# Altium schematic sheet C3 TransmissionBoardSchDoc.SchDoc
size A3; SheetNumber: 1; SheetTotal: 1; ENG_APP_DATE: --/--/--; DSN_APP_DATE: --/--/--; CHK_APP_DATE: --/--/--
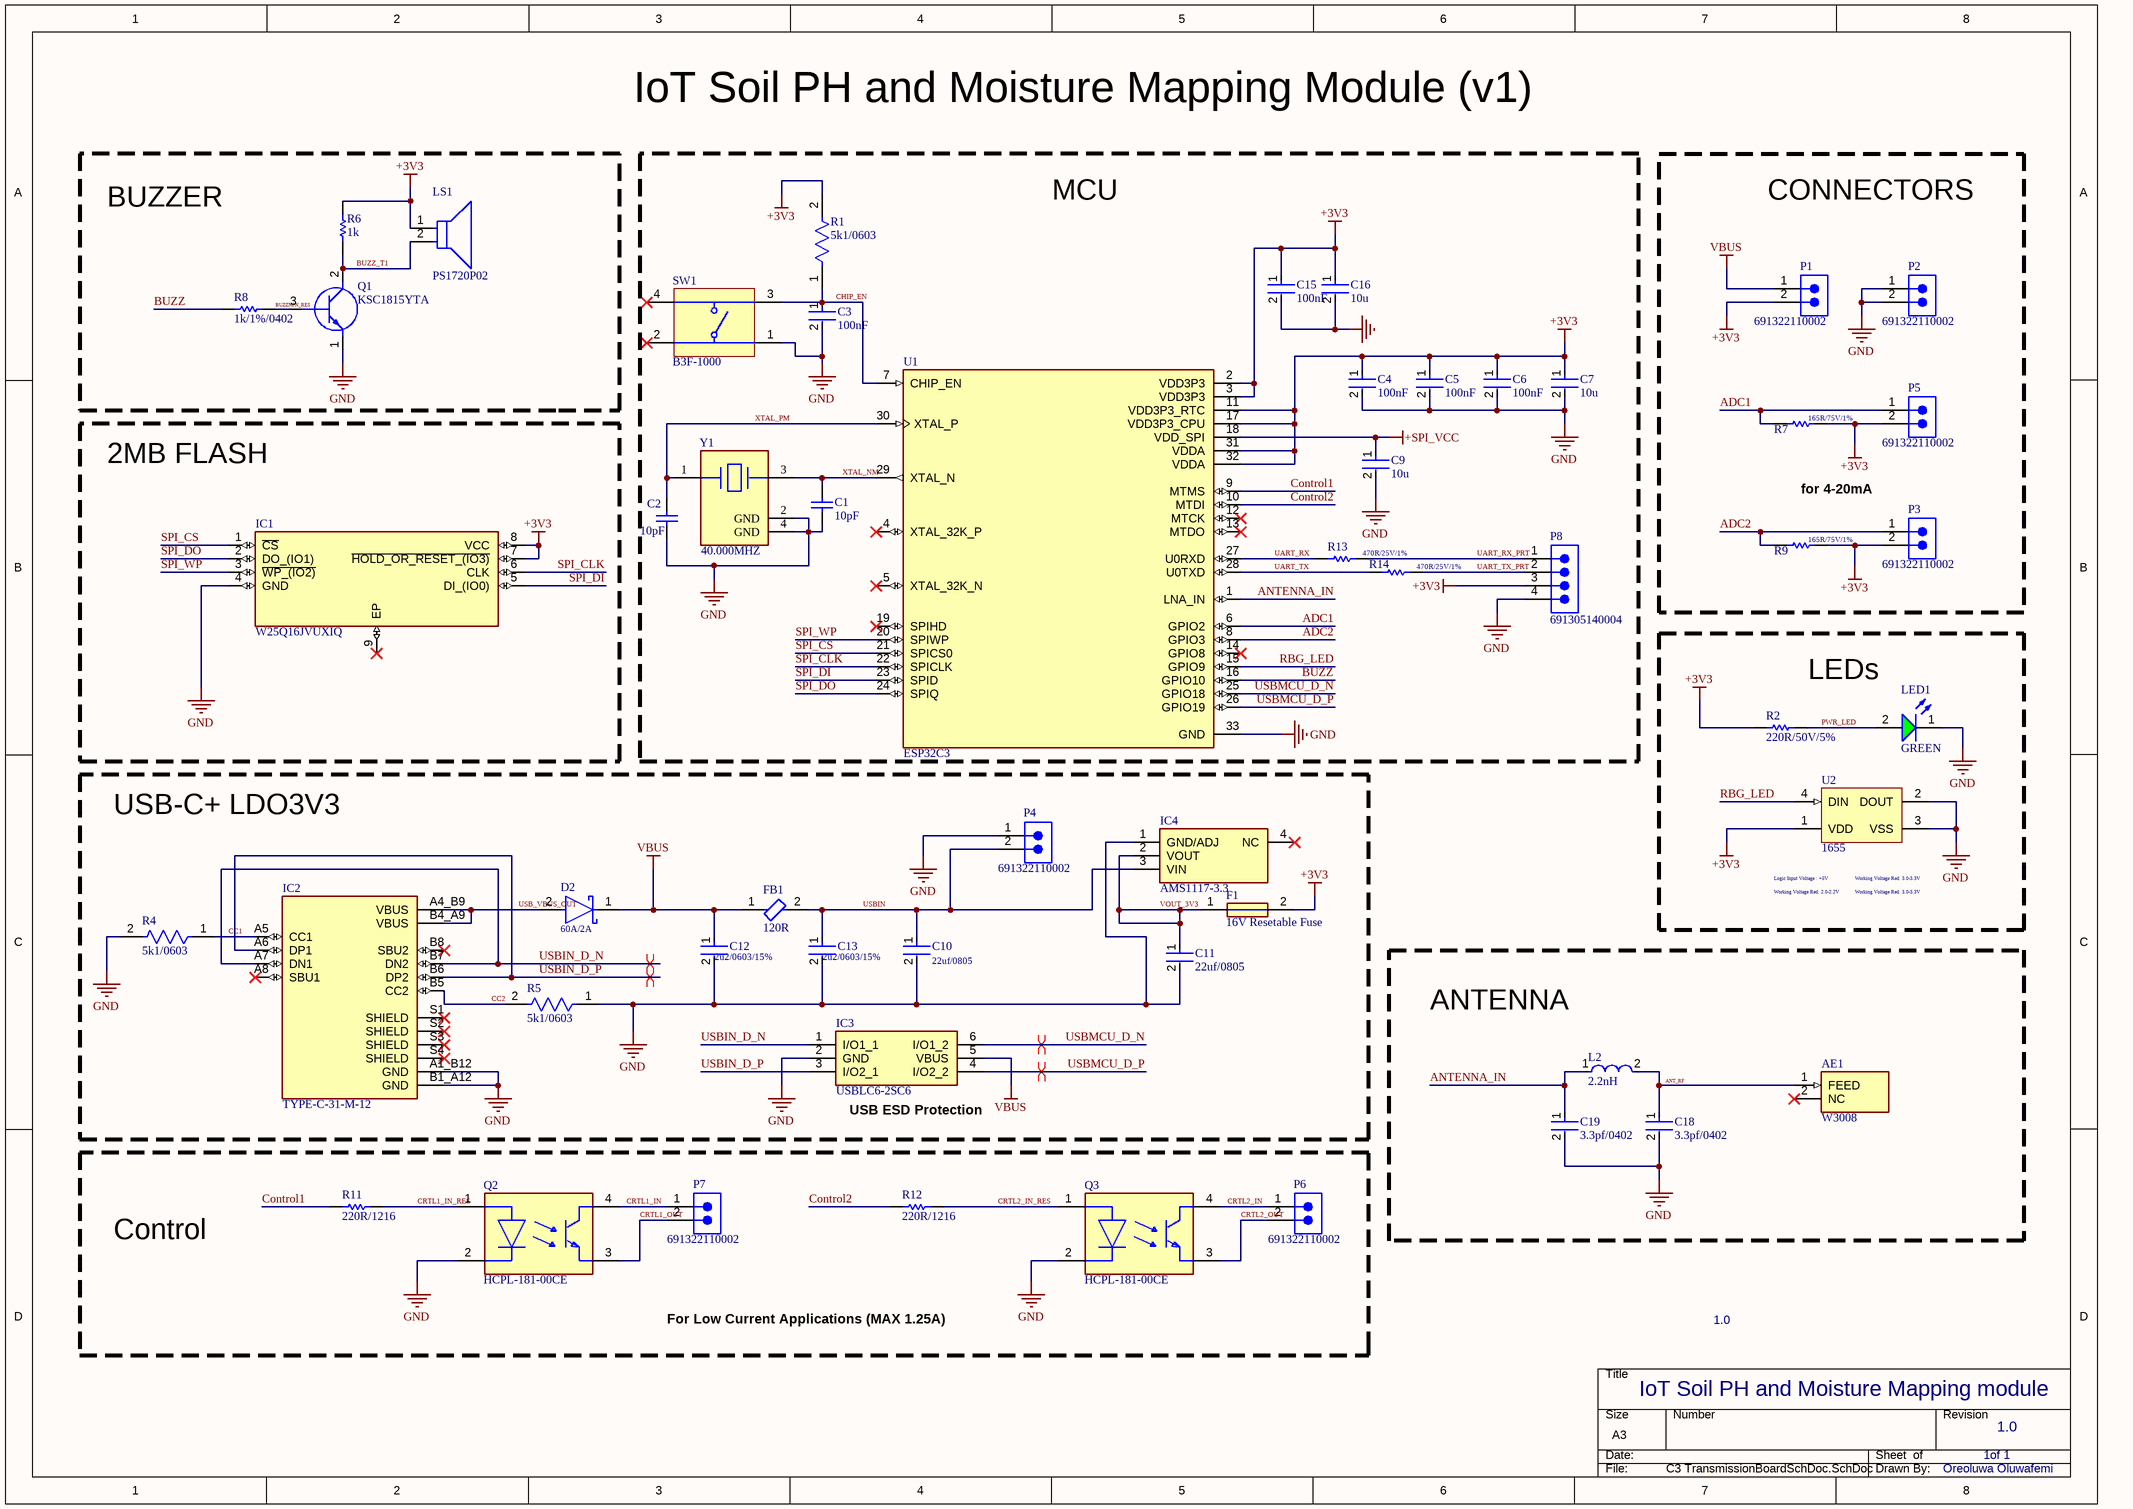
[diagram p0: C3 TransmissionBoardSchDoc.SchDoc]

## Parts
AE1  W3008  [ANTC3216X115N]
C1  10pF  [CAPC1608X90X35LL10T15]
C2  10pF  [CAPC1608X90X35LL10T15]
C3  100nF  [FP-GRM033-0_03-MFG]
C4  100nF  [FP-GRM033-0_03-MFG]
C5  100nF  [FP-GRM033-0_03-MFG]
C6  100nF  [FP-GRM033-0_03-MFG]
C7  10u  [FP-GRM188-0_1-e0_2_0_55-IPC_A]
C9  10u  [FP-GRM188-0_1-e0_2_0_55-IPC_A]
C10  22uf/0805  [FP-C0805C226M9PACTU-MFG]
C11  22uf/0805  [FP-C0805C226M9PACTU-MFG]
C12  2u2/0603/15%  [FP-GRM188-0_1-e0_2_0_5-MFG]
C13  2u2/0603/15%  [FP-GRM188-0_1-e0_2_0_5-MFG]
C15  100nF  [FP-GRM033-0_03-MFG]
C16  10u  [FP-GRM188-0_1-e0_2_0_55-IPC_A]
C18  3.3pf/0402  [FP-GJM155-0_05-IPC_B]
C19  3.3pf/0402  [FP-GJM155-0_05-IPC_B]
D2  60A/2A  [FP-SOD123W-MFG]
F1  16V Resetable Fuse  [FUSC4632X160N]
FB1  120R  [FP-BLM18-0_15-t0_8-IPC_A]
IC1  W25Q16JVUXIQ  [SON50P300X200X60-9N]
IC2  TYPE-C-31-M-12  [HRO_TYPE-C-31-M-12]
IC3  USBLC6-2SC6  [SOT95P280X145-6N]
IC4  AMS1117-3.3  [SOT229P700X180-4N]
L2  2.2nH  [FP-LQW18AN_80-MFG]
LED1  GREEN  [WL-SMCW_0603_150060xx75000]
LS1  PS1720P02  [FP-PS1720P02-MFG]
P1  691322110002  [691322110002]
P2  691322110002  [691322110002]
P3  691322110002  [691322110002]
P4  691322110002  [691322110002]
P5  691322110002  [691322110002]
P6  691322110002  [691322110002]
P7  691322110002  [691322110002]
P8  691305140004  [691305140004]
Q1  KSC1815YTA  [BC33740TA]
Q2  HCPL-181-00CE  [FP-SO-4-MFG]
Q3  HCPL-181-00CE  [FP-SO-4-MFG]
R1  5k1/0603  [FP-RT0603-MFG]
R2  220R/50V/5%  [RESC1005X40X25NL05T10]
R4  5k1/0603  [FP-RT0603-MFG]
R5  5k1/0603  [FP-RT0603-MFG]
R6  1k  [RESC1005X40X25NL05T05]
R7  165R/75V/1%  [RESC1608X55X30NL15T15]
R8  1k/1%/0402  [RESC1005X40X25NL05T05]
R9  165R/75V/1%  [RESC1608X55X30NL15T15]
R11  220R/1216  [RESC3216X60X45ML10T20]
R12  220R/1216  [RESC3216X60X45ML10T20]
R13  470R/25V/1%  [RESC0603X26X15LL03T05]
R14  470R/25V/1%  [RESC0603X26X15LL03T05]
SW1  B3F-1000  [OMRON-B3F-1000-4_V]
U1  ESP32C3  [QFN32_5X5MM]
U2  1655  [ADA-RGB-1655_V]
Y1  40.000MHZ  [FP-ABM8-MFG]

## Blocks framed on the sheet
MCU: C1-C7 C9 C15 C16 P8 R1 R13 R14 SW1 U1 Y1
CONNECTORS: P1-P3 P5 R7 R9
2MB FLASH: IC1
USB-C+ LDO3V3: C10-C13 D2 F1 FB1 IC2-IC4 P4 R4 R5
Control: P6 P7 Q2 Q3 R11 R12

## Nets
+3V3: C4.1 C5.1 C6.1 C7.1 C15.1 C16.1 F1.2 IC1.7(~{HOLD_OR_RESET_(IO3)}) IC1.8(VCC) LS1.1 P1.2 P3.2 P5.2 P8.3 R1.2 R2.1 R6.2 R7.2 R9.2 U1.2(VDD3P3) U1.3(VDD3P3) U1.11(VDD3P3_RTC) U1.17(VDD3P3_CPU) U1.31(VDDA) U1.32(VDDA) U2.1(VDD)
+SPI_VCC: C9.1 U1.18(VDD_SPI)
GND: C1.1 C2.1 C3.2 C4.2 C5.2 C6.2 C7.2 C9.2 C10.2 C11.2 C12.2 C13.2 C15.2 C16.2 C18.2 C19.2 IC1.4(GND) IC2.A1_B12(GND) IC2.B1_A12(GND) IC3.2(GND) IC4.1(GND/ADJ) LED1.1(K) P2.1 P2.2 P4.1 P8.4 Q1.1(E) Q2.2(C) Q3.2(C) R4.2 R5.1 SW1.1 U1.33(GND) U2.2(DOUT) U2.3(VSS) Y1.2(GND) Y1.4(GND)
VBUS: C12.1 D2.1(C) FB1.1 IC3.5(VBUS) P1.1
ADC1: P5.1 R7.1 U1.6(GPIO2)
ADC2: P3.1 R9.1 U1.8(GPIO3)
ANT_RF: AE1.1(FEED) C18.1 L2.2
ANTENNA_IN: C19.1 L2.1 U1.1(LNA_IN)
BUZZ: R8.2 U1.16(GPIO10)
BUZZ_T1: LS1.2 Q1.2(C) R6.1
BUZZNPN_RES: Q1.3(B) R8.1
CC1: IC2.A5(CC1) R4.1
CC2: IC2.B5(CC2) R5.2
CHIP_EN: C3.1 R1.1 SW1.3 U1.7(CHIP_EN)
Control1: R11.1 U1.9(MTMS)
Control2: R12.1 U1.10(MTDI)
CRTL1_IN: P7.1 Q2.4(C)
CRTL1_IN_RES: Q2.1(A) R11.2
CRTL1_OUT: P7.2 Q2.3(E)
CRTL2_IN: P6.1 Q3.4(C)
CRTL2_IN_RES: Q3.1(A) R12.2
CRTL2_OUT: P6.2 Q3.3(E)
PWR_LED: LED1.2(A) R2.2
RBG_LED: U1.15(GPIO9) U2.4(DIN)
SPI_CLK: IC1.6(CLK) U1.22(SPICLK)
SPI_CS: IC1.1(~{CS}) U1.21(SPICS0)
SPI_DI: IC1.5(DI_(IO0)) U1.23(SPID)
SPI_DO: IC1.2(DO_(IO1)) U1.24(SPIQ)
SPI_WP: IC1.3(~{WP_(IO2)}) U1.20(SPIWP)
UART_RX: R13.1 U1.27(U0RXD)
UART_RX_PRT: P8.1 R13.2
UART_TX: R14.1 U1.28(U0TXD)
UART_TX_PRT: P8.2 R14.2
USB_VBUS_OUT: D2.2(A) IC2.A4_B9(VBUS) IC2.B4_A9(VBUS)
USBIN: C10.1 C13.1 FB1.2 IC4.3(VIN) P4.2
USBIN_D_N: IC2.A7(DN1) IC2.B7(DN2) IC3.1(I/O1_1)
USBIN_D_P: IC2.A6(DP1) IC2.B6(DP2) IC3.3(I/O2_1)
USBMCU_D_N: IC3.6(I/O1_2) U1.25(GPIO18)
USBMCU_D_P: IC3.4(I/O2_2) U1.26(GPIO19)
VOUT_3V3: C11.1 F1.1 IC4.2(VOUT)
XTAL_NM: C1.2 U1.29(XTAL_N) Y1.3
XTAL_PM: C2.2 U1.30(XTAL_P) Y1.1

Not connected (* = marked no-connect by the designer): AE1 2(NC)*; IC1 9(EP)*; IC2 A8(SBU1)* B8(SBU2)* S1(SHIELD)* S2(SHIELD)* S3(SHIELD)* S4(SHIELD)*; IC4 4(NC)*; SW1 2* 4*; U1 4(XTAL_32K_P)* 5(XTAL_32K_N)* 12(MTCK)* 13(MTDO)* 14(GPIO8)* 19(SPIHD)*

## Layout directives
differential pair; differential pair class DIF_USB: USBIN_D_N, USBIN_D_P, USBMCU_D_N, USBMCU_D_P

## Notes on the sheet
- IoT Soil PH and Moisture Mapping Module (v1)
- BUZZER
- for 4-20mA
- LEDs
- (near U2) Logic Input Voltage : +5V
- Working Voltage Red: 2.0-2.2V
- (near U2) Working Voltage Red: 3.0-3.3V
- Working Voltage Red: 3.0-3.3V
- ANTENNA
- (near IC3) USB ESD Protection
- For Low Current Applications (MAX 1.25A)
- 1.0
- IoT Soil PH and Moisture Mapping module
- 1of 1
- Oreoluwa Oluwafemi

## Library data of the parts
AE1 = W3008: Antenna; Manufacturer_Name: PULS
C1 C2 = CMP-2006-02592-1: Part Number: GRM1885C1H100JA01D; Manufacturer: Murata
C3-C6 C15 = CMP-06035-000062-2: Chip Multilayer Ceramic Capacitors for General Purpose, 0201, 0.10uF, X5R, 15%, 10%, 6.3V
C7 C9 C16 = CMP-2006-02792-2: Chip Multilayer Ceramic Capacitors for General Purpose, 0603, 10uF, X5R, 15%, 20%, 6.3V
C10 C11 = CMP-2007-01021-2: CAP CER 22UF 6.3V X5R 0805; Tolerance: 20%; Dielectric Material: Ceramic; Dissipation Factor: 5%
C12 C13 = CMP-2006-02836-2: Chip Multilayer Ceramic Capacitors for General Purpose, 0603, 2.2uF, X7R, 15%, 10%, 10V
C18 C19 = CMP-2008-03847-2: Multi-Layer Ceramic Capacitor 3.3pF C0G  ±0.25pF 0402 Paper T/R; Voltage: 50V
D2 = CMP-14398-000040-1: DIODE SCHOTTKY 60V 2A CFP3
F1 = MF-MSMF250_16X: Fuse; Manufacturer_Name: Bourns; Manufacturer_Part_Number: MF-MSMF250/16X
FB1 = CMP-0686-00557-7: Chip Ferrite Bead, 0603, 120Ω @ 100MHz, 0.05Ω, 25%, 2A; Number of Circuits: 1; Shielding: Unshielded; Material: Steel; DC Resistance (DCR): 50mR
IC1 = CMP-031-00015-1: NOR Flash Serial (SPI, Dual SPI, Quad SPI) 3V/3.3V 16M-bit 2M x 8 6ns 8-Pin USON EP T/R; MF: Winbond
IC2 = CMP-002-00071-1: USB Connectors 24 Receptacle 1 8.94*7.3mm RoHS; MF: HRO Electronics Co., Ltd.
IC3 = USBLC6-2SC6: Integrated Circuit; Manufacturer_Name: STMicroelectronics
IC4 = AMS1117-3.3: Integrated Circuit; Manufacturer_Name: Advanced
L2 = CMP-06042-009804-1: Wire Wound RF Inductor 2.2nH ±0.2nH 3200mA 0.018Ω 0603 (1608); Test Frequency: 100MHz; DC Resistance (DCR): 18mR; Self Resonant Frequency: 15GHz; Shielding: Unshielded; Current Rating: 3.2A
LED1 = CMP-1426-00006-6: NexarPartId: 29717778; Reverse Voltage: 5V; Forward Voltage: 2V; Viewing Angle: 140°; Luminous Intensity: 40mcd; Test Current: 20mA; Max Junction Temperature (Tj): 95°C; Wavelength: 570nm; Forward Current: 100mA; Lens Style: Clear, Rectangular; Power Dissipation: 72mW; Peak Wavelength: 572nm
LS1 = CMP-08413-000001-1: AUDIO PIEZO TRANSDUCER 30V TH; Manufacturer: TDK Corporation; Frequency: 2kHz; Standoff Height: 0.5mm
P1-P7 = CMP-1502-01791-3: NexarPartId: 18818346; Voltage Rating: 300V; Number of Contacts: 2; Gender: Male; Current: 10A; Number of Levels: 1; Pitch: 3.5052mm
P8 = CMP-1502-01777-2: NexarPartId: 78871379; Gender: Male
Q1 = CMP-030-000000-1: Transistor; Manufacturer_Name: onsemi
Q2 Q3 = CMP-18400-000021-1: OPTOISO 3.75KV TRANS 4MINIFLAT; Manufacturer: Broadcom; Min Current Transfer Ratio: 200%; Isolation Voltage: 3750Vrms; Turn Off Delay Time: 4us; Turn On Delay Time: 3us; Reverse Voltage: 6V; Standoff Height: 0mm; Forward Voltage: 1.2V; Power Dissipation: 170mW; Collector Emitter Voltage: 80V; Max Current Transfer Ratio: 400%; Forward Current: 20mA
R1 R4 R5 = CMP-2000-04778-2: RES SMD 5.1K OHM 1% 1/10W 0603; Manufacturer: Yageo; Manufacturer Part Number: RT0603FRE075K1L; Value: 5.1KΩ; Temperature Coefficient: 50 ppm/°C; Power Rating: 0.1W; Voltage Rating: 75V; Tolerance: 0.01
R2 = CMP-2002-07959-1: Manufacturer: Yageo / Phycomp; Part Number: RC0402JR-07220RL
R6 R8 = CMP-1011-00510-4: Chip Resistor, 1 KOhm, +/- 1%, 100 mW, -55 to 155 degC, 0402 (1005 Metric), RoHS, Tape and Reel; PartNumber: ERJ-2RKF1001X; Manufacturer: Basic Passives; Voltage Rating: 50 V; Case\/Package: 0402; Resistance: 1 KOhm; Power Rating: 100 mW
R7 R9 = CMP-2000-00277-1: Manufacturer: Panasonic; Part Number: ERJ-3EKF1650V
R11 R12 = CMP-2003-01956-1: Manufacturer: Vishay Dale; Part Number: CRCW1206220RFKEA
R13 R14 = CMP-1010-00379-2: Manufacturer: Panasonic; Part Number: ERJ1GNF4700C
SW1 = CMP-1677-00002-1: Tactile Switch, SPST-NO, 0.05 A, 5 to 24 V, -25 to 70 degC, 4-Pin THD, RoHS, Bulk; Shielding: Shielded; Gender: Female; Capacitance: -45 f; Voltage Rating: 150 V; Current Rating: 1.5 A
U1 = CMP-031-00006-1: WiFi Modules (802.11) (Engineering Samples Only) SMD IC ESP32-C3, RISC-V single-core MCU, 2.4G Wi-Fi & BLE 5.0 combo, QFN 32-pin, 5*5 mm, 40 ~ 105C; MF: Espressif Systems
U2 = CMP-2000-05026-1: Intelligent Control LED Integrated Light Source, 3.5 to 5.3 V, -25 to 80 degC, 4-Pin SMD, RoHS, Tape and Reel; Manufacturer: Adafruit-Industries-LLC; Number of LEDs: 10; Configuration: Discrete; Utilized LED: WS2812(5050)
Y1 = CMP-27762-008947-1: Crystal 40MHz ±10ppm 10pF SMD-4 3.2mm x 2.5mm; ESR (Equivalent Series Resistance): 35R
